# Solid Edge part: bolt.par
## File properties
Author: Robert a Rhodes jr
Template: Normal.par
Last saved by: Cadcim
Revision: 9
Application: Solid Edge
Accuracy: 0.99
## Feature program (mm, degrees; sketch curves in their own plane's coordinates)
sketch for "unnamed RevolvedProtrusion 1" plane through (0, 0, 0) normal (0, -1, 0) x-axis (1, 0, 0)
  line (0, 40.7664) -> (14.7729, 40.7664)
  line (14.7729, 40.7664) -> (14.7729, 29.2752)
  line (14.7729, 29.2752) -> (8, 29.2752)
  line (8, 29.2752) -> (8, -6.0192)
  line (8, -6.0192) -> (0, -6.0192)
  line (0, -6.0192) -> (0, 40.7664)
  dimension (linear) = 8
revolve "unnamed RevolvedProtrusion 1" add full turn 360 deg
sketch for "unnamed Cutout 1" plane through (0, 0, 40.7664) normal (0, 0, 1) x-axis (1, 0, 0)
  line (-7.0309, 0) -> (-3.9268, 6.0697)
  line (-3.9268, 6.0697) -> (3.076, 6.0697)
  line (3.076, 6.0697) -> (7.0309, 0)
  line (7.0309, 0) -> (3.2724, -6.223)
  line (3.2724, -6.223) -> (-3.2724, -6.223)
  line (-3.2724, -6.223) -> (-7.0309, 0)
extrude "unnamed Cutout 1" cut finite 6.35 along -normal
chamfer "Chamfer_1" setback 2
thread "Thread_1"  ThreadDepth = 15 mm
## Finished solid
Body 1: solid body, 14 faces, 24 edges, 12 vertices.
  Faces by surface: plane 10, cylinder 3, cone 1
  Edges by curve: line 18, circle 6
Bounding box of the edges (mm): 29.546 x 29.546 x 46.786, from (-14.7729, -14.7729, -6.0192) to (14.7729, 14.7729, 40.7664).
Cylindrical faces by radius (mm): R8 x2, R14.7729 x1
Conical faces (half-angle, radius in mm at the cone's reference point): 45 deg R12.7729 x1
Planar faces by outward normal: +y 1, +z 2, -y 1, -z 2, oblique 4
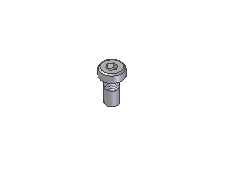
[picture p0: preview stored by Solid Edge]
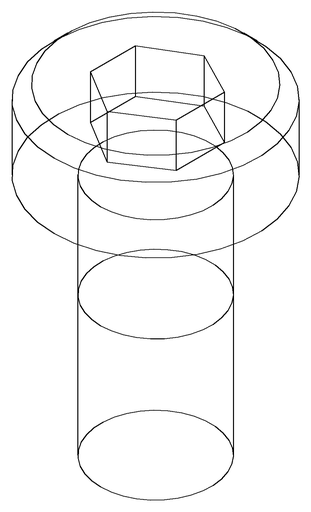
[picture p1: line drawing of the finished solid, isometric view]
